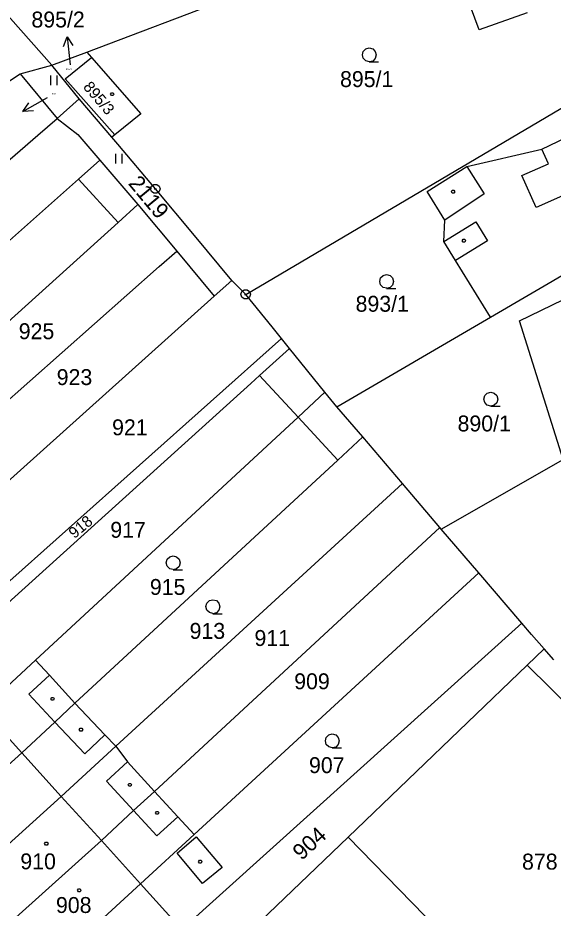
# Model space of a CAD drawing. Extents: x -609861 to -605046, y -1120287 to -1116307.
# Drawn here: x -607692.7 to -607635.6, y -1118821.7 to -1118726.7 of the extents above; entities that cross this region are included whole.
import ezdxf

# ---------------------------------------------------------------- set-up
doc = ezdxf.new("R2010")
doc.units = 0
for name, color, linetype in [('Vrstva 1', 7, 'Continuous'), ('Vrstva 2', 7, 'Continuous'), ('Vrstva 3', 7, 'Continuous'), ('Vrstva 4', 7, 'Continuous'), ('Vrstva 5', 7, 'Continuous'), ('Vrstva 7', 7, 'Continuous'), ('Vrstva 8', 7, 'Continuous')]:
    doc.layers.add(name, color=color, linetype=linetype)

msp = doc.modelspace()

# ---------------------------------------------------------------- linework, layer by layer
at = {"layer": 'Vrstva 1'}
for p, q in [((-607685.32, -1118730.35), (-607647.76, -1118716.1)), ((-607643.47, -1118727.98), (-607647.76, -1118716.1)), ((-607689.06, -1118731.77), (-607694.59, -1118725.52)), ((-607638.35, -1118726.15), (-607643.47, -1118727.98)), ((-607668.37, -1118756.22), (-607622.36, -1118729.05)), ((-607689.06, -1118731.77), (-607685.32, -1118730.35)), ((-607685.32, -1118730.35), (-607684.81, -1118730.92)), ((-607687.62, -1118733.2), (-607684.81, -1118730.92)), ((-607684.81, -1118730.92), (-607679.54, -1118736.94)), ((-607692.43, -1118732.69), (-607689.06, -1118731.77)), ((-607686.15, -1118735.35), (-607689.06, -1118731.77)), ((-607695.52, -1118734.7), (-607692.43, -1118732.69)), ((-607692.43, -1118732.69), (-607688.5, -1118737.46)), ((-607682.34, -1118739.2), (-607687.62, -1118733.2)), ((-607688.5, -1118737.46), (-607686.15, -1118735.35)), ((-607682.65, -1118739.45), (-607686.15, -1118735.35)), ((-607679.54, -1118736.94), (-607682.34, -1118739.2)), ((-607690.54, -1118739.22), (-607688.5, -1118737.46)), ((-607688.5, -1118737.46), (-607686.29, -1118739.14)), ((-607636.77, -1118740.72), (-607630.98, -1118737.95)), ((-607716.21, -1118761.39), (-607690.54, -1118739.22)), ((-607686.29, -1118739.14), (-607683.92, -1118741.88)), ((-607682.34, -1118739.2), (-607682.65, -1118739.45)), ((-607682.02, -1118740.2), (-607682.65, -1118739.45)), ((-607678.01, -1118744.97), (-607682.02, -1118740.2)), ((-607644.78, -1118742.57), (-607636.77, -1118740.72)), ((-607686.21, -1118743.92), (-607683.92, -1118741.88)), ((-607649, -1118745.22), (-607644.78, -1118742.57)), ((-607711.26, -1118766.13), (-607686.21, -1118743.92)), ((-607686.21, -1118743.92), (-607681.96, -1118748.53)), ((-607673.83, -1118749.92), (-607678.01, -1118744.97)), ((-607647.13, -1118748.28), (-607649, -1118745.22)), ((-607681.96, -1118748.53), (-607679.86, -1118746.64)), ((-607679.86, -1118746.64), (-607675.72, -1118751.59)), ((-607647.22, -1118750.59), (-607647.13, -1118748.28)), ((-607706.72, -1118770.88), (-607681.96, -1118748.53)), ((-607669.84, -1118754.73), (-607673.83, -1118749.92)), ((-607645.99, -1118752.6), (-607647.22, -1118750.59)), ((-607677.6, -1118753.26), (-607675.72, -1118751.59)), ((-607675.72, -1118751.59), (-607671.73, -1118756.42)), ((-607642.25, -1118758.65), (-607631.19, -1118752.18)), ((-607642.25, -1118758.65), (-607645.99, -1118752.6)), ((-607702.49, -1118775.31), (-607677.6, -1118753.26)), ((-607671.73, -1118756.42), (-607669.84, -1118754.73)), ((-607668.37, -1118756.22), (-607669.84, -1118754.73)), ((-607639.16, -1118759.06), (-607630.64, -1118754.92)), ((-607698.06, -1118780.04), (-607671.73, -1118756.42)), ((-607665.56, -1118759.7), (-607668.37, -1118756.22)), ((-607658.64, -1118768.24), (-607642.25, -1118758.65)), ((-607664.55, -1118760.94), (-607665.56, -1118759.7)), ((-607634.48, -1118773.83), (-607639.16, -1118759.06)), ((-607715.24, -1118806.12), (-607664.55, -1118760.94)), ((-607663.7, -1118761.99), (-607664.55, -1118760.94)), ((-607659.91, -1118766.66), (-607663.7, -1118761.99)), ((-607667.83, -1118765.73), (-607666.88, -1118764.87)), ((-607662.78, -1118769.31), (-607666.88, -1118764.87)), ((-607700.88, -1118795.63), (-607667.83, -1118765.73)), ((-607658.64, -1118768.24), (-607659.91, -1118766.66)), ((-607655.86, -1118771.43), (-607658.64, -1118768.24)), ((-607690.8, -1118795.26), (-607662.78, -1118769.31)), ((-607658.54, -1118773.91), (-607662.78, -1118769.31)), ((-607658.54, -1118773.91), (-607655.86, -1118771.43)), ((-607651.64, -1118776.4), (-607655.86, -1118771.43)), ((-607686.6, -1118799.87), (-607658.54, -1118773.91)), ((-607647.5, -1118781.28), (-607634.48, -1118773.83)), ((-607682.23, -1118804.46), (-607651.64, -1118776.4)), ((-607647.64, -1118781.09), (-607651.64, -1118776.4)), ((-607678.09, -1118809.27), (-607647.64, -1118781.09)), ((-607647.5, -1118781.28), (-607647.64, -1118781.09)), ((-607643.49, -1118785.95), (-607647.5, -1118781.28)), ((-607673.87, -1118813.89), (-607643.49, -1118785.95)), ((-607638.92, -1118791.33), (-607643.49, -1118785.95)), ((-607675.2, -1118824), (-607638.92, -1118791.33)), ((-607637.86, -1118792.54), (-607638.92, -1118791.33)), ((-607636.53, -1118794.06), (-607637.86, -1118792.54)), ((-607636.53, -1118794.06), (-607638.34, -1118795.79)), ((-607635.5, -1118795.23), (-607636.53, -1118794.06)), ((-607696.46, -1118800.51), (-607690.8, -1118795.26)), ((-607638.34, -1118795.79), (-607657.45, -1118814.15)), ((-607638.34, -1118795.79), (-607615.48, -1118818.48)), ((-607696.46, -1118800.51), (-607692.25, -1118805.15)), ((-607688.74, -1118801.9), (-607686.6, -1118799.87)), ((-607692.25, -1118805.15), (-607688.74, -1118801.9)), ((-607688.05, -1118809.8), (-607682.23, -1118804.46)), ((-607682.23, -1118804.46), (-607680.97, -1118806.12)), ((-607701.39, -1118813.36), (-607692.25, -1118805.15)), ((-607692.25, -1118805.15), (-607688.05, -1118809.8)), ((-607680.97, -1118806.12), (-607678.09, -1118809.27)), ((-607697.15, -1118818.04), (-607688.05, -1118809.8)), ((-607680.33, -1118811.31), (-607678.09, -1118809.27)), ((-607678.09, -1118809.27), (-607675.61, -1118811.99)), ((-607683.77, -1118814.53), (-607680.33, -1118811.31)), ((-607675.61, -1118811.99), (-607673.87, -1118813.89)), ((-607679.58, -1118819.15), (-607673.87, -1118813.89)), ((-607692.89, -1118822.73), (-607683.77, -1118814.53)), ((-607657.45, -1118814.15), (-607668.07, -1118824.35)), ((-607657.45, -1118814.15), (-607635.08, -1118837.06)), ((-607688.65, -1118827.4), (-607679.58, -1118819.15)), ((-607679.58, -1118819.15), (-607675.2, -1118824))]:
    msp.add_line(p, q, dxfattribs=at)
at = {"layer": 'Vrstva 3'}
for p, q in [((-607689.19, -1118732.84), (-607689.19, -1118733.89)), ((-607688.49, -1118733.89), (-607688.49, -1118732.84)), ((-607682.25, -1118741.2), (-607682.25, -1118742.25)), ((-607681.55, -1118742.25), (-607681.55, -1118741.2))]:
    msp.add_line(p, q, dxfattribs=at)
for points in [[(-607655.17, -1118731.39), (-607655.55, -1118731.29), (-607655.82, -1118731.02), (-607655.92, -1118730.65), (-607655.82, -1118730.28), (-607655.55, -1118730.01), (-607655.18, -1118729.91), (-607654.81, -1118730.01), (-607654.54, -1118730.28), (-607654.44, -1118730.66), (-607654.54, -1118731.04), (-607654.81, -1118731.31), (-607655.19, -1118731.41), (-607654.19, -1118731.41)], [(-607653.32, -1118755.57), (-607653.7, -1118755.47), (-607653.97, -1118755.2), (-607654.07, -1118754.83), (-607653.97, -1118754.46), (-607653.7, -1118754.19), (-607653.33, -1118754.09), (-607652.96, -1118754.19), (-607652.69, -1118754.46), (-607652.59, -1118754.84), (-607652.69, -1118755.22), (-607652.96, -1118755.49), (-607653.34, -1118755.59), (-607652.34, -1118755.59)], [(-607642.21, -1118768.14), (-607642.59, -1118768.04), (-607642.86, -1118767.77), (-607642.96, -1118767.4), (-607642.86, -1118767.03), (-607642.59, -1118766.76), (-607642.22, -1118766.66), (-607641.85, -1118766.76), (-607641.58, -1118767.03), (-607641.48, -1118767.41), (-607641.58, -1118767.79), (-607641.85, -1118768.06), (-607642.23, -1118768.16), (-607641.23, -1118768.16)], [(-607676.1, -1118785.6), (-607676.48, -1118785.5), (-607676.75, -1118785.23), (-607676.85, -1118784.86), (-607676.75, -1118784.49), (-607676.48, -1118784.22), (-607676.11, -1118784.12), (-607675.74, -1118784.22), (-607675.47, -1118784.49), (-607675.37, -1118784.87), (-607675.47, -1118785.25), (-607675.74, -1118785.52), (-607676.12, -1118785.62), (-607675.12, -1118785.62)], [(-607671.86, -1118790.29), (-607672.24, -1118790.19), (-607672.51, -1118789.92), (-607672.61, -1118789.55), (-607672.51, -1118789.18), (-607672.24, -1118788.91), (-607671.87, -1118788.81), (-607671.5, -1118788.91), (-607671.23, -1118789.18), (-607671.13, -1118789.56), (-607671.23, -1118789.94), (-607671.5, -1118790.21), (-607671.88, -1118790.31), (-607670.88, -1118790.31)], [(-607659.12, -1118804.62), (-607659.5, -1118804.52), (-607659.77, -1118804.25), (-607659.87, -1118803.88), (-607659.77, -1118803.51), (-607659.5, -1118803.24), (-607659.13, -1118803.14), (-607658.76, -1118803.24), (-607658.49, -1118803.51), (-607658.39, -1118803.89), (-607658.49, -1118804.27), (-607658.76, -1118804.54), (-607659.14, -1118804.64), (-607658.14, -1118804.64)]]:
    msp.add_lwpolyline(points, dxfattribs=at)
at = {"layer": 'Vrstva 4'}
for p, q in [((-607636.07, -1118742.28), (-607636.77, -1118740.72)), ((-607683.92, -1118741.88), (-607679.86, -1118746.64)), ((-607644.78, -1118742.57), (-607642.94, -1118745.5)), ((-607638.9, -1118743.54), (-607636.07, -1118742.28)), ((-607637.37, -1118746.95), (-607638.9, -1118743.54)), ((-607642.94, -1118745.5), (-607647.13, -1118748.28)), ((-607634.55, -1118745.69), (-607637.37, -1118746.95)), ((-607647.22, -1118750.59), (-607643.81, -1118748.49)), ((-607643.81, -1118748.49), (-607642.57, -1118750.49)), ((-607642.57, -1118750.49), (-607645.99, -1118752.6)), ((-607666.88, -1118764.87), (-607663.7, -1118761.99)), ((-607662.78, -1118769.31), (-607659.91, -1118766.66)), ((-607690.8, -1118795.26), (-607689.32, -1118796.88)), ((-607691.52, -1118798.88), (-607689.32, -1118796.88)), ((-607689.32, -1118796.88), (-607686.6, -1118799.87)), ((-607688.74, -1118801.9), (-607691.52, -1118798.88)), ((-607683.41, -1118803.22), (-607686.6, -1118799.87)), ((-607688.74, -1118801.9), (-607685.54, -1118805.26)), ((-607685.54, -1118805.26), (-607683.41, -1118803.22)), ((-607682.23, -1118804.46), (-607683.41, -1118803.22)), ((-607680.97, -1118806.12), (-607683.21, -1118808.17)), ((-607683.21, -1118808.17), (-607680.33, -1118811.31)), ((-607688.05, -1118809.8), (-607683.77, -1118814.53)), ((-607680.33, -1118811.31), (-607677.84, -1118814.03)), ((-607677.84, -1118814.03), (-607675.61, -1118811.99)), ((-607683.77, -1118814.53), (-607679.58, -1118819.15)), ((-607675.68, -1118815.86), (-607673.65, -1118814.13)), ((-607673.65, -1118814.13), (-607670.87, -1118817.39)), ((-607672.96, -1118819.12), (-607675.68, -1118815.86)), ((-607670.87, -1118817.39), (-607672.96, -1118819.12))]:
    msp.add_line(p, q, dxfattribs=at)
at = {"layer": 'Vrstva 5'}
for points in [[(-607682.52, -1118734.69), (-607682.43, -1118734.84), (-607682.52, -1118734.99), (-607682.7, -1118734.99), (-607682.79, -1118734.84), (-607682.7, -1118734.69)], [(-607646.15, -1118745.11), (-607646.06, -1118745.26), (-607646.15, -1118745.41), (-607646.33, -1118745.41), (-607646.42, -1118745.26), (-607646.33, -1118745.11)], [(-607644.99, -1118750.34), (-607644.9, -1118750.49), (-607644.99, -1118750.64), (-607645.17, -1118750.64), (-607645.26, -1118750.49), (-607645.17, -1118750.34)], [(-607688.88, -1118799.25), (-607688.79, -1118799.4), (-607688.88, -1118799.55), (-607689.06, -1118799.55), (-607689.15, -1118799.4), (-607689.06, -1118799.25)], [(-607685.85, -1118802.53), (-607685.76, -1118802.68), (-607685.85, -1118802.83), (-607686.03, -1118802.83), (-607686.12, -1118802.68), (-607686.03, -1118802.53)], [(-607680.64, -1118808.42), (-607680.55, -1118808.57), (-607680.64, -1118808.72), (-607680.82, -1118808.72), (-607680.91, -1118808.57), (-607680.82, -1118808.42)], [(-607677.72, -1118811.41), (-607677.63, -1118811.56), (-607677.72, -1118811.71), (-607677.9, -1118811.71), (-607677.99, -1118811.56), (-607677.9, -1118811.41)], [(-607689.55, -1118814.7), (-607689.46, -1118814.85), (-607689.55, -1118815), (-607689.73, -1118815), (-607689.82, -1118814.85), (-607689.73, -1118814.7)], [(-607673.13, -1118816.63), (-607673.04, -1118816.78), (-607673.13, -1118816.93), (-607673.31, -1118816.93), (-607673.4, -1118816.78), (-607673.31, -1118816.63)], [(-607686.04, -1118819.68), (-607685.95, -1118819.83), (-607686.04, -1118819.98), (-607686.22, -1118819.98), (-607686.31, -1118819.83), (-607686.22, -1118819.68)]]:
    msp.add_lwpolyline(points, close=True, dxfattribs=at)
at = {"layer": 'Vrstva 7'}
for p, q in [((-607687.427, -1118728.72), (-607687.08, -1118731.7)), ((-607692.132, -1118736.704), (-607689.53, -1118735.21))]:
    msp.add_line(p, q, dxfattribs=at)
for points in [[(-607687.808, -1118729.771), (-607687.427, -1118728.72), (-607686.815, -1118729.656)], [(-607691.015, -1118736.639), (-607692.132, -1118736.704), (-607691.513, -1118735.772)]]:
    msp.add_lwpolyline(points, dxfattribs=at)
at = {"layer": 'Vrstva 8'}
for p, q in [((-607678.13, -1118744.97), (-607677.89, -1118744.97)), ((-607668.49, -1118756.22), (-607668.25, -1118756.22))]:
    msp.add_line(p, q, dxfattribs=at)
for points in [[(-607677.86, -1118744.49), (-607677.61, -1118744.67), (-607677.51, -1118744.96), (-607677.61, -1118745.25), (-607677.86, -1118745.43), (-607678.17, -1118745.43), (-607678.42, -1118745.25), (-607678.52, -1118744.96), (-607678.42, -1118744.67), (-607678.17, -1118744.49)], [(-607668.22, -1118755.74), (-607667.97, -1118755.92), (-607667.87, -1118756.21), (-607667.97, -1118756.5), (-607668.22, -1118756.68), (-607668.53, -1118756.68), (-607668.78, -1118756.5), (-607668.88, -1118756.21), (-607668.78, -1118755.92), (-607668.53, -1118755.74)]]:
    msp.add_lwpolyline(points, close=True, dxfattribs=at)

# ---------------------------------------------------------------- texts
at = {"layer": 'Vrstva 2'}
for s, height, p in [('895/2', 0.2, (-607687.562, -1118732.28)), ('895/1', 1.7, (-607658.303, -1118734.09)), ('932', 0.2, (-607689.052, -1118734.91)), ('893/1', 1.7, (-607656.643, -1118758.07)), ('925', 1.7, (-607692.583, -1118761)), ('923', 1.7, (-607688.533, -1118765.9)), ('890/1', 1.7, (-607645.763, -1118770.85)), ('921', 1.7, (-607682.623, -1118771.26)), ('917', 1.7, (-607682.813, -1118782.2)), ('915', 1.7, (-607678.593, -1118788.3)), ('913', 1.7, (-607674.353, -1118792.99)), ('911', 1.7, (-607667.433, -1118793.75)), ('909', 1.7, (-607663.193, -1118798.37)), ('907', 1.7, (-607661.613, -1118807.32)), ('910', 1.7, (-607692.413, -1118817.59)), ('878', 1.7, (-607638.883, -1118817.62)), ('908', 1.7, (-607688.613, -1118822.25))]:
    msp.add_text(s, height=height, dxfattribs=at).set_placement(p)
for s, height, rotation, p in [('895/3', 1.2, 310.48583, (-607685.781, -1118734.117)), ('2119', 1.7, 309.62639, (-607680.969, -1118744.413)), ('918', 1.2, 39.59138, (-607686.641, -1118782.343)), ('904', 1.7, 42.28429, (-607662.404, -1118816.71))]:
    msp.add_text(s, height=height, rotation=rotation, dxfattribs=at).set_placement(p)
at = {"layer": 'Vrstva 7'}
msp.add_text('895/2', height=1.7, dxfattribs=at).set_placement((-607691.23, -1118727.73))

doc.saveas('drawing.dxf')
